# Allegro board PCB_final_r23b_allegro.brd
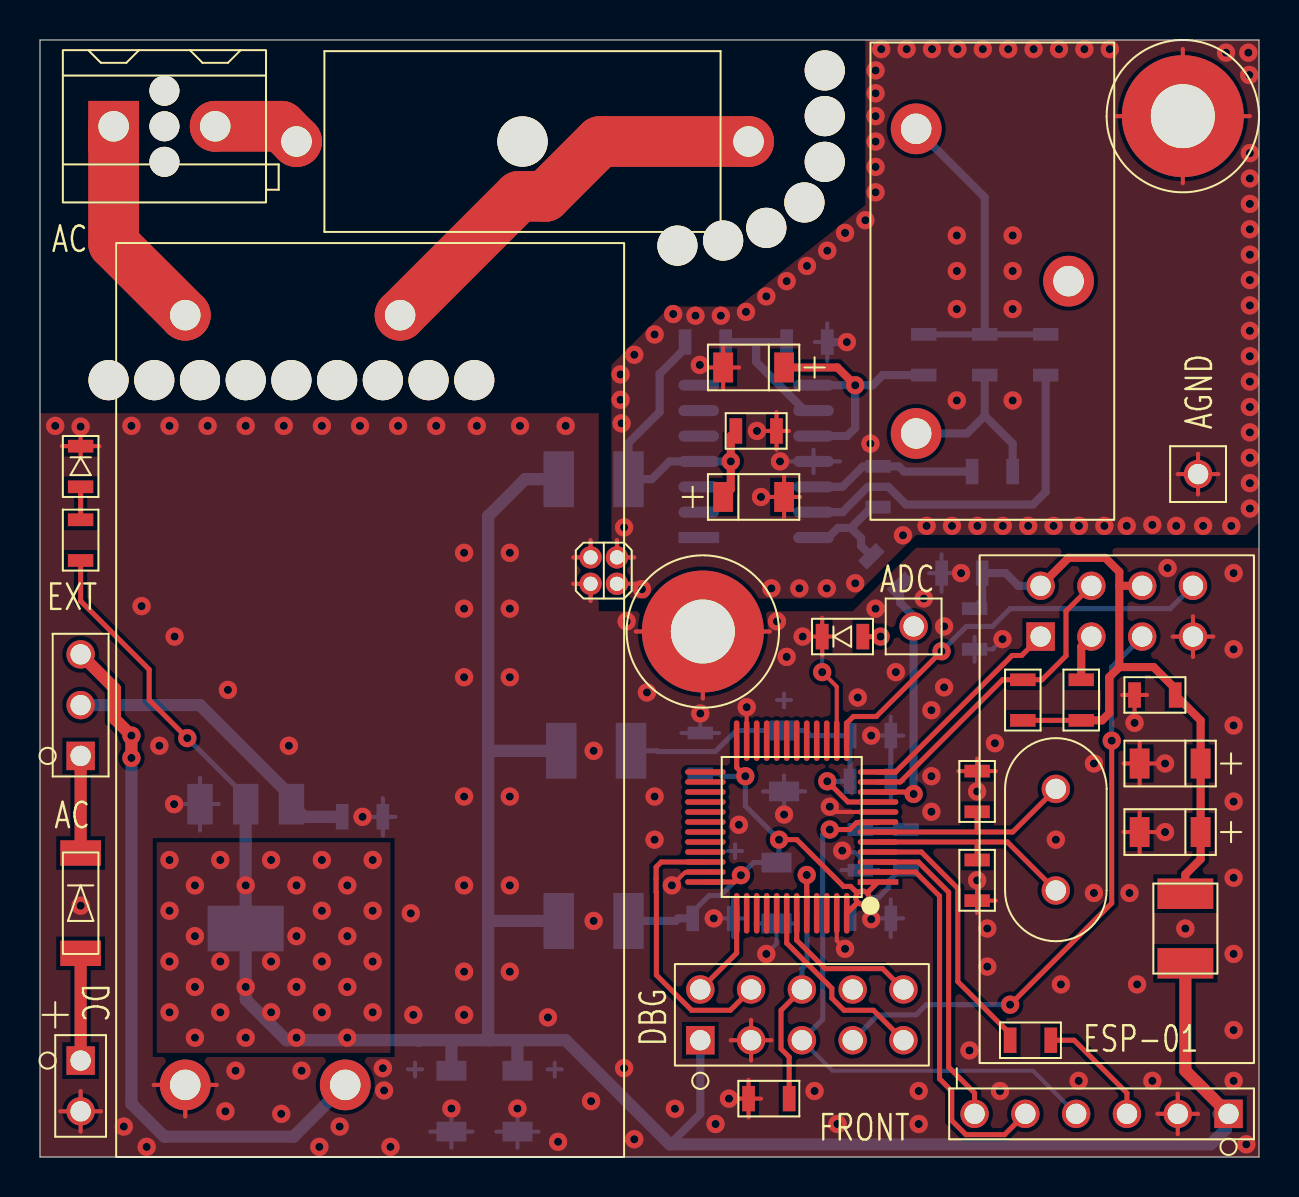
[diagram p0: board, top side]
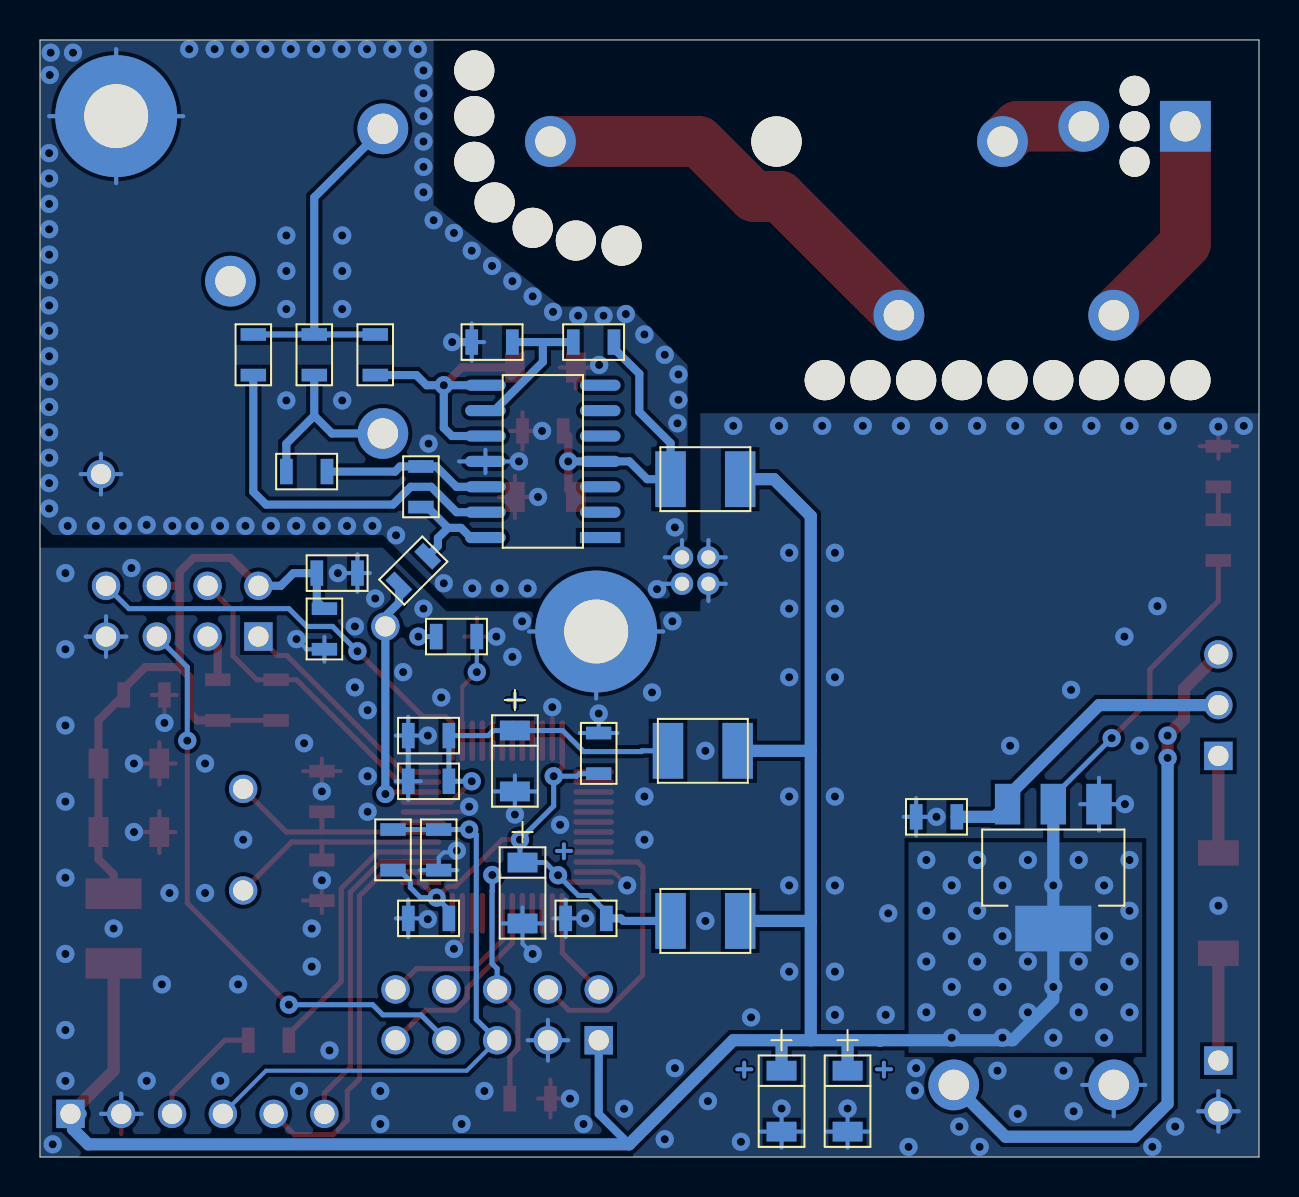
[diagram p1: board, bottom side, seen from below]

Outline 60.96 x 55.88 mm; copper layers: TOP, IN1, IN2, BOTTOM. Coordinates in mm from the lower left corner of the outline.
Outline path: 0,55.88 0,0 60.96,0 60.96,55.88 0,55.88

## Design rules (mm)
net group DP1: nets USB_DM USB_DP

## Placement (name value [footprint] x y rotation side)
C4  100n  [S_0805]  16.13 17.02 0 bottom
C5  10u  [S_1206_CAP]  23.88 2.79 270 bottom
C8  10u  [S_1206_CAP]  36.83 13.21 270 bottom
C9  100n  [S_0805]  33.66 11.94 0 bottom
C10  100n  [S_0805]  41.53 11.94 0 bottom
C11  100n  [S_0805]  33.02 20.19 90 bottom
C12  100n  [S_0805]  41.02 15.37 270 bottom
C16  10u  [S_1206_CAP]  35.69 39.5 180 top
C17  22p  [S_0805]  46.86 13.84 270 top
C18  22p  [S_0805]  46.86 18.29 90 top
C22  100n  [S_0805]  35.81 36.32 0 top
C23  10n  [S_0805]  46.74 26.42 270 bottom
C24  10u  [S_1206_CAP]  56.52 19.68 180 top
C25  10u  [S_1206_CAP]  20.57 2.79 270 bottom
C26  100n  [S_0805]  55.75 23.11 180 top
C27  100n  [S_0805]  46.1 29.21 180 bottom
C28  10u  [S_1206_CAP]  35.69 33.02 0 top
C29  10u  [S_1206_CAP]  37.21 19.81 270 bottom
C30  10n  [S_0805]  41.53 21.08 0 bottom
C31  100n  [S_0805]  41.53 18.8 0 bottom
C32  10u  [S_1206_CAP]  56.52 16.26 180 top
D1  SUF4007  [S_MELF]  2.03 12.7 270 top
F1  FUSEHOLDER  [T_FUSE]  24.13 50.8 0 top
H1  MOUNT HOLE M3  [MOUNT_HOLE_M3]  57.15 52.07 0 top
H2  MOUNT HOLE M3  [MOUNT_HOLE_M3]  33.15 26.29 0 top
J1  AC  [T_POWER_CON]  6.22 51.56 0 top
J2  PWR_SELECT  [T_SIP3]  2.03 22.61 180 top
J3  EXT_12V  [T_SIP2]  2.03 4.83 0 top
J16  FRONT  [T_SIP6]  59.44 2.16 270 top
J17  DEBUG_PORT  [T_HEADER5X2]  38.1 7.11 90 top
L2  27uH  [S_1210]  27.69 33.91 0 bottom
L4  27uH  [S_1210]  27.69 11.81 0 bottom
L5  27uH  [S_1210]  57.28 11.43 90 top
L6  27uH  [S_1210]  27.81 20.32 0 bottom
LD1  D1  [S_0805_LED]  40.13 26.04 0 top
LD3  POWER  [S_0805_LED]  2.03 34.54 270 top
NOREF  -  [unnamed]  21.72 38.86 0 top
NOREF#2  -  [unnamed]  10.29 38.86 0 top
NOREF#3  -  [unnamed]  5.71 38.86 0 top
NOREF#4  -  [unnamed]  36.32 46.48 0 top
NOREF#5  -  [#2]  0 0 0 top
NOREF#6  -  [unnamed]  39.24 52.07 0 top
NOREF#7  -  [unnamed]  8 38.86 0 top
NOREF#8  -  [unnamed]  39.24 49.78 0 top
NOREF#9  -  [unnamed]  19.43 38.86 0 top
NOREF#10  -  [#2]  0 0 90 top
NOREF#11  -  [unnamed]  12.57 38.86 0 top
NOREF#12  -  [unnamed]  14.86 38.86 0 top
NOREF#13  -  [unnamed]  3.43 38.86 0 top
NOREF#14  -  [unnamed]  38.23 47.75 0 top
NOREF#15  -  [unnamed]  31.88 45.59 0 top
NOREF#16  -  [unnamed]  39.24 54.36 0 top
NOREF#17  -  [unnamed]  34.16 45.85 0 top
NOREF#18  -  [unnamed]  17.14 38.86 0 top
R3  470  [S_0805]  40.13 26.04 0 bottom
R5  150  [S_0805]  2.03 30.86 90 top
R6  100R  [S_0805]  47.24 40.13 270 bottom
R7  10k  [S_0805]  47.62 34.29 180 bottom
R8  100k  [S_0805]  41.91 33.53 270 bottom
R9  470R  [S_0805]  42.29 29.34 315 bottom
R10  1K  [S_0805]  33.27 40.77 0 bottom
R11  1K  [S_0805]  38.35 40.77 0 bottom
R19  10k  [S_0805]  36.45 2.92 0 top
R20  100k  [S_0805]  49.15 22.86 270 top
R21  100k  [S_0805]  52.07 22.86 270 top
R22  100k  [S_0805]  43.31 15.37 90 bottom
R23  470  [S_0805]  49.53 5.84 180 top
R24  470R  [S_0805]  44.2 40.13 270 bottom
R25  10k  [S_0805]  50.29 40.13 270 bottom
SB1  AGND BRIDGE  [T_AGND_BRIDGE]  28.19 29.34 180 top
TP1  TEST POINT  [T_TESTPOINT]  43.69 26.54 0 top
TP2  TEST POINT  [T_TESTPOINT]  57.91 34.16 0 top
TR1  AC-1010  [T_TALEMA_CUR_TR]  47.62 43.81 90 top
U1  MeanWell IRM-10-12  [T_MEANWELL_PSU]  16.51 22.86 270 top
U3  LD1117AS33TR  [S_SOT223]  10.29 17.65 270 bottom
U5  STM32F303CC  [S_LQFP48]  37.59 16.51 180 top
U6  ESP-01  [ESP01]  53.85 27.3 90 top
U7  AD8544  [S_SOIC14_N]  35.81 34.8 0 bottom
X1  8MHz  [T_XTAL50]  50.8 15.88 90 top

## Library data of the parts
C4 C9-C12 C17 C18 C22 C23 C26 C27 C30 C31 = CAPACITOR NON-POL
C5 C8 C16 C24 C25 C28 C29 C32 = CAP POL
D1 = DIODE
F1 = FUSEHOLDER
H1 H2 = MOUNT HOLE M3
J1 J3 = HEADER 2
J2 = JUMPER 3
J16 = HEADER 6
J17 = HEADER 5X2
L2 L4-L6 = INDUCTOR
LD1 LD3 = LED
R3 R5-R11 R19-R25 = RESISTOR
SB1 = AGND BRIDGE
TP1 TP2 = TEST POINT
TR1 = ac-1010
U1 = meanwell_psu
U3 = LD1117AS33TR
U5 = stm32f303cct6
U6 = ESP-01
U7 = AD8544
X1 = CRYSTAL

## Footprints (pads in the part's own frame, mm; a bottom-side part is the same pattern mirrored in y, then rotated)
ESP01
  rect 1.422x1.422 hole 1.016: 1(-1.27,3.81)
  round 1.422 hole 1.016: 2(1.27,3.81) 3(-1.27,1.27) 4(1.27,1.27) 5(-1.27,-1.27) 6(1.27,-1.27) 7(-1.27,-3.81) 8(1.27,-3.81)
MOUNT_HOLE_M3
  round 6.096 hole 3.2: 1(0,0)
S_0805
  rect 0.635x1.27 smd: 1(-1.016,0) 2(1.016,0)
S_0805_LED
  rect 0.635x1.27 smd: 1(-1.016,0) 2(1.016,0)
S_1206_CAP
  rect 0.991x1.499 smd: 1(-1.524,0) 2(1.524,0)
S_1210
  rect 1.524x2.794 smd: 1(-1.742,0) 2(1.742,0)
S_LQFP48
  rect 2.032x0.279 smd: 1(-4.318,2.752)
  oval 2.032x0.279 smd: 2(-4.318,2.252) 3(-4.318,1.751) 4(-4.318,1.251) 5(-4.318,0.751) 6(-4.318,0.25) 7(-4.318,-0.25) 8(-4.318,-0.751) 9(-4.318,-1.251) 10(-4.318,-1.751) 11(-4.318,-2.252) 12(-4.318,-2.752) 25(4.318,-2.752) 26(4.318,-2.252) 27(4.318,-1.751) 28(4.318,-1.251) 29(4.318,-0.751) 30(4.318,-0.25) 31(4.318,0.25) 32(4.318,0.751) 33(4.318,1.251) 34(4.318,1.751) 35(4.318,2.252) 36(4.318,2.752)
  oval 0.279x2.032 smd: 13(-2.752,-4.318) 14(-2.252,-4.318) 15(-1.751,-4.318) 16(-1.251,-4.318) 17(-0.751,-4.318) 18(-0.25,-4.318) 19(0.25,-4.318) 20(0.751,-4.318) 21(1.251,-4.318) 22(1.751,-4.318) 23(2.252,-4.318) 24(2.752,-4.318) 37(2.752,4.318) 38(2.252,4.318) 39(1.751,4.318) 40(1.251,4.318) 41(0.751,4.318) 42(0.25,4.318) 43(-0.25,4.318) 44(-0.751,4.318) 45(-1.251,4.318) 46(-1.751,4.318) 47(-2.252,4.318) 48(-2.752,4.318)
S_MELF
  rect 1.27x2.032 smd: 1(-2.51,0) 2(2.51,0)
S_SOIC14_N
  rect 2.032x0.559 smd: 1(-2.87,3.81)
  oval 2.032x0.559 smd: 2(-2.87,2.54) 3(-2.87,1.27) 4(-2.87,0) 5(-2.87,-1.27) 6(-2.87,-2.54) 7(-2.87,-3.81) 8(2.87,-3.81) 9(2.87,-2.54) 10(2.87,-1.27) 11(2.87,0) 12(2.87,1.27) 13(2.87,2.54) 14(2.87,3.81)
S_SOT223
  rect 2.032x1.27 smd: 1(0,2.286) 2(0,0) 3(0,-2.286)
  rect 2.286x3.81 smd: 4(6.223,0)
T_AGND_BRIDGE
  round 1.118 hole 0.711: 1(-0.66,0.66) 2(0.66,0.66) 3(-0.66,-0.66) 4(0.66,-0.66)
T_FUSE
  round 2.515 hole 2.54 unplated: (0,0)
  round 2.54 hole 1.524: 1(-11.303,0) 2(11.303,0)
T_HEADER5X2
  rect 1.422x1.422 hole 1.016: 1(-1.27,5.08)
  round 1.422 hole 1.016: 2(1.27,5.08) 3(-1.27,2.54) 4(1.27,2.54) 5(-1.27,0) 6(1.27,0) 7(-1.27,-2.54) 8(1.27,-2.54) 9(-1.27,-5.08) 10(1.27,-5.08)
T_MEANWELL_PSU
  round 2.54 hole 1.524: 1(-19.253,1.499) 2(-19.253,-9.246) 3(19.253,-1.245) 4(19.253,-9.246)
T_POWER_CON
  round 1.499 hole 1.524 unplated: (0,1.778) (0,0) (0,-1.778)
  rect 2.54x2.54 hole 1.524: 1(-2.54,0)
  round 2.54 hole 1.524: 2(2.54,0)
T_SIP2
  rect 1.422x1.422 hole 1.016: 1(0,0)
  round 1.422 hole 1.016: 2(0,-2.54)
T_SIP3
  rect 1.422x1.422 hole 1.016: 1(0,2.54)
  round 1.422 hole 1.016: 2(0,0) 3(0,-2.54)
T_SIP6
  rect 1.422x1.422 hole 1.016: 1(0,0)
  round 1.422 hole 1.016: 2(0,-2.54) 3(0,-5.08) 4(0,-7.62) 5(0,-10.16) 6(0,-12.7)
T_TALEMA_CUR_TR
  round 2.54 hole 1.524: 1(-7.62,3.81) 2(7.62,3.81) X1(0,-3.81)
T_TESTPOINT
  round 1.422 hole 1.016: 1(0,0)
T_XTAL50
  round 1.422 hole 1.016: 1(-2.54,0) 2(2.54,0)
unnamed
  round 2.007 hole 2.032 unplated: (0,0)

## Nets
3V3: C5.1 C25.1 J16.1 J17.1 L2.1 L4.1 L5.1 L6.1 R5.1 U3.2(VOUT) U3.4(TAB_VOUT)
3V3_ADC: C29.1 C30.1 C31.1 L6.2 U5.9(VDDA)
3V3_ANALOG: C22.1 C28.1 L2.2 R10.1 U7.4(VCC)
3V3_CPU: C8.1 C9.1 C10.1 C11.1 L4.2 R22.1 U5.1(VBAT) U5.24(VDD#24) U5.36(VDD#36) U5.48(VDD#48)
3V3_ESP: C23.1 C24.1 C26.1 C27.1 C32.1 L5.2 R20.2 R21.2 U6.2(VCC) U6.6(CHPD)
12V: C4.1 J2.2(P2) U3.3(VIN)
GND: C4.2 C5.2 C8.2 C9.2 C10.2 C11.2 C12.2 C17.2 C18.2 C23.2 C24.2 C25.2 C26.2 C27.2 C29.2 C30.2 C31.2 C32.2 H2.1 J3.2 J16.2 J17.3 LD1.1(CATHODE) LD3.1(CATHODE) R19.1 SB1.2(B1) SB1.4(B2) U1.4(GND) U3.1(GND) U5.8(VSSA) U5.23(VSS#23) U5.35(VSS#35) U5.47(VSS#47) U6.7(GND)
GNDA: C16.2 C22.2 C28.2 H1.1 R11.2 SB1.1(A1) SB1.3(A2) TP2.1 U7.11(GND)
ADC_IN: R9.2 TP1.1 U5.10(PA0)
BOOT0: J17.6 R19.2 U5.44(BOOT0)
BTN_AP: J16.5 U5.2(PC13)
BTN_WPS: J16.6 U5.3(PC14/OSC32_IN)
DBG_RX: J17.10 U5.43(PB7)
DBG_TX: J17.9 U5.42(PB6)
ESP_DBG_TX: J17.7 U6.5(GPIO2)
ESP_NRST: R20.1 U5.11(PA1) U6.4(RST)
ESP_RX: U5.12(PA2) U6.1(RX)
ESP_TX: U5.13(PA3) U6.8(TX)
PA4: R3.1 U5.14(PA4)
PA5: U5.15(PA5)
PA6: U5.16(PA6)
PA7: U5.17(PA7)
PA8: U5.29(PA8)
PA9: U5.30(PA9)
PA10: U5.31(PA10)
PA13: J17.4 U5.34(PA13)
PA14: J17.2 U5.37(PA14)
PA15: U5.38(PA15)
PB0: U5.18(PB0)
PB1: U5.19(PB1)
PB2: U5.20(PB2)
PB3: U5.39(PB3)
PB4: U5.40(PB4)
PB5: U5.41(PB5)
PB8: U5.45(PB8)
PB9: U5.46(PB9)
PB10: U5.21(PB10)
PB11: U5.22(PB11)
PB12: U5.25(PB12)
PB13: U5.26(PB13)
PB14: U5.27(PB14)
PB15: U5.28(PB15)
PC15: R23.2 U5.4(PC15/OSC32_OUT)
STM_NRST: C12.1 J16.4 J17.5 R22.2 U5.7(NRST)
USB_DM: U5.32(PA11)
USB_DP: U5.33(PA12)
N50776: F1.1 J1.2
N50985: J2.3(P3) U1.3(12V)
N125461: R7.2 R8.1 U7.12(P)
N125469: R8.2 R9.1 U7.14(Y)
N125661: R10.2 R11.1 U7.9(N)
N125707: C16.1 R24.2 U7.8(Y) U7.10(P)
N128674: C18.1 U5.6(PF1/OSC_OUT) X1.2
N128682: C17.1 U5.5(PF0/OSC_IN) X1.1
N134498: R21.1 U6.3(GPIO0)
N141672: J16.3 R23.1
N147532: D1.2(A) J3.1
N147956: D1.1(K) J2.1(P1)
N153457: J1.1 U1.2(AC/L)
N158713: R25.2 U7.13(N)
N165035: R6.2 R7.1 TR1.1
N165680: R6.1 R24.1 R25.1 TR1.2
N507430: F1.2 U1.1(AC/N)
N1337610: LD3.2(ANODE) R5.2
N1355460: LD1.2(ANODE) R3.2

Pads without a net: J17 8; TR1 X1; U7 1 2 3 5 6 7

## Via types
v1: diameter 0.914, hole 0.406, TOP to BOTTOM, 257 vias

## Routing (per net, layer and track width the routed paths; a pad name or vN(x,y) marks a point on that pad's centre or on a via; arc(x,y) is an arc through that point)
3V3: length 134
  TOP w0.254: v1(7.37,20.95) 5.46,22.86 5.46,24.38 2.03,27.81 R5.1
  TOP w0.61: L5.1 57.28,4.32 J16.1
  BOTTOM w0.254: U3.2 10.29,18.03 v1(7.37,20.95)
  BOTTOM w0.406: 31.5,0.64 33.02,2.16 J17.1
  BOTTOM w0.61: L6.1 22.42,20.32 22.42,20.32 ; 22.42,20.32 22.42,32.07 24.26,33.91 L2.1 ; 22.42,20.32 22.42,11.81 ; 59.31,1.78 59.31,1.4 58.55,0.64 31.5,0.64 26.29,5.84 23.88,5.84 ; 59.31,1.78 59.31,2.03 J16.1 ; 59.31,1.78 58.93,2.16 ; 20.57,5.84 18.97,5.84 18.95,5.82 18.92,5.84 12.32,5.84 10.29,7.87 ; 20.57,5.84 22.42,5.84 ; 20.57,5.84 C25.1 ; 22.42,5.84 22.42,11.81 ; 22.42,5.84 23.88,5.84 ; 22.42,11.81 L4.1 ; 23.88,5.84 C5.1 ; 10.29,8 v1(10.29,8.51) U3.4 v1(10.29,13.59) U3.2
  vias: v1(6.48,14.86) v1(6.48,12.32) v1(6.48,9.78) v1(6.48,7.24) v1(7.75,13.59) v1(7.75,11.05) v1(7.75,8.51) v1(7.75,5.97) v1(9.02,14.86) v1(9.02,9.78) v1(9.02,7.24) v1(10.29,5.97) v1(11.56,14.86) v1(11.56,9.78) v1(11.56,7.24) v1(12.83,13.59) v1(12.83,11.05) v1(12.83,8.51) v1(12.83,5.97) v1(14.1,14.86) v1(14.1,12.32) v1(14.1,9.78) v1(14.1,7.24) v1(15.37,13.59) v1(15.37,11.05) v1(15.37,8.51) v1(15.37,5.97) v1(16.64,14.86) v1(16.64,12.32) v1(16.64,9.78) v1(16.64,7.24)
3V3_ADC: length 17.9
  TOP w0.254: U5.9 40.41,17.76 v1(39.37,18.8)
  BOTTOM w0.254: L6.2 30.86,20.32 30.9,20.28 33.77,20.28 34.83,21.34 C29.1 38.29,21.34 38.54,21.08 40.51,21.08 40.51,18.8 v1(39.37,18.8)
3V3_ANALOG: length 17.1
  TOP w0.406: C22.1 34.54,36.07 v1(34.54,34.8) 34.54,33.4 C28.1
  BOTTOM w0.406: v1(34.54,34.8) U7.4 31.49,34.8 30.6,33.91 L2.2 29.43,35.71 30.99,37.27 30.99,39.18 32.26,40.45 R10.1
3V3_CPU: length 31.9
  TOP w0.254: v1(35.05,14.1) 34.71,13.76 U5.36 ; v1(35.27,19.05) 34.84,19.48 U5.24 ; U5.1 41.13,12.97 ; 41.13,12.97 U5.48 ; 41.13,12.97 v1(41.13,12.97) 40.81,13.29 40.79,13.29 40.54,13.54 40.18,13.54 37.85,15.88 v1(36.96,15.88)
  BOTTOM w0.254: C11.1 33.99,19.18 34.11,19.05 v1(35.27,19.05) 35.27,17.56 v1(36.96,15.88) 36.96,14.86 C8.1 35.69,14.73 v1(35.05,14.1) 34.04,13.08 33.46,13.08 32.64,12.26 C9.1 ; R22.1 42.99,14.35 42.44,13.8 42.44,13.48 41.93,12.97 v1(41.13,12.97) 40.51,12.36 40.51,11.94
  BOTTOM w0.406: C9.1 31.92,11.94 31.79,11.81 L4.2
3V3_ESP: length 37.2
  TOP w0.254: R20.2 R21.2
  TOP w0.406: 53.98,24.51 53.47,24 53.47,22.2 53.11,21.84 R21.2 ; 53.98,24.51 55.69,24.51 56.77,23.43 C26.1 58.04,21.84 C24.1 C32.1 58.04,14.9 57.28,14.14 L5.2 ; 53.98,24.51 53.98,28.57 ; 53.98,28.57 53.98,29.27 53.27,29.97 51.44,29.97 U6.2 ; 53.98,28.57 U6.6
  BOTTOM w0.406: U6.2 48.92,28.57 48.29,29.21 C27.1 47.12,27.81 C23.1
12V: length 15.6
  BOTTOM w0.61: 15.11,17.02 13.21,17.02 U3.3 12.57,18.03 8,22.61 J2.2
GND: length 155.7
  TOP w0.203: 7.26,2.03 U1.4 ; U1.4 8.84,3.61 ; U1.4 5.69,3.61 ; v1(39.5,17.53) 39.76,17.26 U5.8 ; 55.88,2.16 J16.2 ; J16.2 56.9,1.14 ; J16.2 57.91,2.16 ; J16.2 56.9,3.18 ; v1(54.74,21.72) C26.2 ; C26.2 54.11,23.11 ; C26.2 55.36,23.11 ; v1(56.26,19.68) C24.2 ; C24.2 54.19,19.68 ; C24.2 54.99,20.74 ; C24.2 54.99,18.63 ; U5.35 32.29,14.26 32.24,14.2 32.21,14.2 31.6,13.59 v1(31.6,13.59) ; 29.79,26.29 H2.1 ; H2.1 36.5,26.29 ; H2.1 33.15,22.94 ; 34.54,5.84 J17.3 ; J17.3 35.56,4.83 ; J17.3 35.56,6.86 ; J17.3 36.58,5.84 ; J3.2 3.05,2.29 ; J3.2 2.03,1.27 ; J3.2 2.03,3.3 ; J3.2 1.02,2.29 ; LD3.1 v1(2.03,36.54) ; LD3.1 2.03,34.94 ; LD3.1 1.09,35.56 ; LD3.1 2.97,35.56 ; v1(56.26,16.26) C32.2 ; C32.2 54.99,15.2 ; C32.2 54.99,17.31 ; C32.2 54.19,16.26 ; U6.7 57.66,27.05 ; U6.7 56.64,26.04 ; U6.7 58.67,26.04 ; U6.7 57.66,25.02 ; LD1.1 39.74,26.04 ; LD1.1 v1(38.14,26.04) ; LD1.1 39.12,26.98 ; LD1.1 39.12,25.09 ; C18.2 46.86,19.93 ; C18.2 v1(46.86,18.29) ; C18.2 47.8,19.3 ; C18.2 45.92,19.3 ; R19.1 36.06,2.92 ; R19.1 35.43,3.86 ; R19.1 v1(34.46,2.92) ; R19.1 35.43,1.98 ; 46.86,12.2 C17.2 ; C17.2 v1(46.86,13.84) ; C17.2 47.8,12.83 ; U5.23 v1(35.34,22.5) ; 27.53,30.86 SB1.4 26.67,30 ; 26.67,28.68 SB1.2 27.53,27.81 ; U5.47 39.84,10.83 v1(40.26,10.41)
  BOTTOM w0.203: C9.2 34.67,12.88 ; C9.2 35.29,11.94 ; C9.2 34.67,11 ; C9.2 v1(33.69,11.94) ; 19.52,1.27 C25.2 ; C25.2 20.57,0.47 ; C25.2 21.63,1.27 ; C25.2 v1(20.57,2.43) ; C29.2 38.27,18.29 ; C29.2 36.16,18.29 ; C29.2 v1(37.21,17.13) ; C29.2 37.21,19.09 ; C12.2 41.02,14.99 40.77,15.24 40.26,15.24 40.17,15.33 v1(40.12,15.33) ; C12.2 40.08,14.35 ; C12.2 41.96,14.35 ; C23.2 47.62,25.4 ; C23.2 46.74,24.78 ; C23.2 46.74,26.02 ; 47.62,25.4 v1(48.13,25.91) ; 47.62,25.4 47.68,25.4 ; 8,17.65 v1(6.71,17.65) ; 8,17.65 8,18.97 ; 8,17.65 8,16.33 ; 8,17.65 8.94,17.65 ; U1.4 8.84,3.61 ; U1.4 5.69,3.61 ; U1.4 7.26,2.03 ; H2.1 36.5,26.29 ; H2.1 33.15,22.94 ; H2.1 29.79,26.29 ; 26.67,30 SB1.4 27.53,30.86 ; C30.2 43.17,21.08 ; C30.2 v1(41.57,21.08) ; C30.2 42.55,22.02 ; J16.2 56.9,3.18 ; J16.2 57.91,2.16 ; J16.2 55.88,2.16 ; 23.88,0.47 C5.2 ; C5.2 24.93,1.27 ; C5.2 22.82,1.27 ; C5.2 v1(23.88,2.43) ; 17.14,17.02 17.77,17.02 ; 17.14,17.02 v1(16.13,17.02) ; 17.14,17.02 17.14,17.96 ; 17.14,17.02 17.14,16.08 ; 42.55,17.86 C31.2 ; C31.2 43.17,18.8 ; C31.2 41.92,18.8 ; 57.66,25.02 U6.7 ; U6.7 57.66,27.05 ; U6.7 58.67,26.04 ; U6.7 56.64,26.04 ; C27.2 v1(46.06,29.21) ; C27.2 45.09,28.27 ; C27.2 45.09,30.15 ; C27.2 44.46,29.21 ; C10.2 42.55,12.88 ; C10.2 42.55,11 ; C10.2 43.17,11.94 ; C10.2 41.57,11.94 v1(41.57,11.89) ; C8.2 37.88,11.68 ; C8.2 36.83,10.67 v1(36.32,10.16) ; C8.2 36.83,12.48 ; C8.2 35.78,11.68 ; J17.3 35.56,6.86 ; J17.3 34.54,5.84 ; J17.3 35.56,4.83 ; J17.3 36.58,5.84 ; 1.02,2.29 J3.2 ; J3.2 2.03,3.3 ; J3.2 2.03,1.27 ; J3.2 3.05,2.29 ; 27.53,27.81 SB1.2 26.67,28.68 ; 33.02,21.21 33.96,21.21 ; 33.02,21.21 32.08,21.21 ; 33.02,21.21 v1(33.02,22.19)
  BOTTOM w0.254: C31.2 C30.2
  vias: v1(0.76,36.58) v1(2.03,12.57) v1(4.19,1.52) v1(4.57,36.58) v1(5.08,27.56) v1(5.33,0.51) v1(5.97,20.57) v1(6.48,36.58) v1(6.73,26.04) v1(8.38,36.58) v1(9.27,2.29) v1(9.4,23.37) v1(9.78,4.32) v1(10.29,36.58) v1(12.06,2.16) v1(12.19,36.58) v1(12.45,20.57) v1(13.08,4.32) v1(13.97,0.51) v1(14.1,36.58) v1(14.99,1.52) v1(16,36.58) v1(17.14,4.45) v1(17.21,3.33) v1(17.53,0.51) v1(17.91,36.58) v1(18.54,12.19) v1(18.67,7.11) v1(19.81,36.58) v1(21.21,30.23) v1(21.21,27.43) v1(21.21,24) v1(21.21,18.03) v1(21.21,13.59) v1(21.21,9.27) v1(21.21,7.11) v1(21.84,36.58) v1(23.5,30.23) v1(23.5,27.43) v1(23.5,24) v1(23.5,18.03) v1(23.5,13.59) v1(23.5,9.27) v1(24,36.58) v1(25.4,6.99) v1(25.91,0.76) v1(26.29,36.58) v1(27.56,2.79) v1(27.69,20.32) v1(27.69,11.81) v1(29.21,4.45) v1(29.34,26.8) v1(29.72,0.89) v1(30.35,23.24) v1(30.73,18.03) v1(30.73,15.88) v1(31.75,2.41) v1(33.78,1.65) v1(34.95,16.62) v1(36.85,26.8) v1(37.34,25.02) v1(38.73,3.3) v1(39.88,1.65) v1(40.89,22.99) v1(41.78,27.43) v1(42.8,24.26) v1(43.94,3.3) v1(43.94,1.65) v1(44.2,27.94) v1(44.58,22.35) v1(44.58,19.05) v1(44.58,17.27) v1(45.21,26.54) v1(45.21,23.5) v1(46.48,5.33) v1(47.37,11.43) v1(47.37,9.53) v1(47.75,20.7) v1(48.01,3.3) v1(50.8,15.88) v1(51.05,8.64) v1(51.94,3.81) v1(52.7,19.68) v1(52.7,13.21) v1(54.48,13.21) v1(54.86,8.64) v1(55.63,3.81) v1(56.39,29.46) v1(57.28,11.43) v1(59.69,29.21) v1(59.69,25.4) v1(59.69,21.59) v1(59.69,17.78) v1(59.69,13.97) v1(59.69,10.16) v1(59.69,6.35) v1(59.69,3.81) v1(60.33,0.64)
GNDA: length 59.7
  TOP w0.203: C16.2 33.26,39.5 33.13,39.62 v1(33,39.62) ; C16.2 34.16,40.55 ; C16.2 34.96,39.5 ; C16.2 34.16,38.44 ; C28.2 38.01,33.02 ; C28.2 37.21,34.07 ; C28.2 v1(36.06,33.02) ; C28.2 37.21,31.97 ; H1.1 57.15,55.42 ; H1.1 60.5,52.07 ; H1.1 57.15,48.72 ; H1.1 53.8,52.07 ; SB1.1 29.82,28.68 ; C22.2 v1(35.85,36.32) ; C22.2 37.45,36.32 ; C22.2 36.83,35.38 ; C22.2 36.83,37.26 ; 56.9,34.16 TP2.1 ; TP2.1 57.91,33.15 ; TP2.1 58.93,34.16 ; TP2.1 57.91,35.18 ; 28.85,30.86 SB1.3 29.72,30
  BOTTOM w0.203: U7.11 40.01,34.8 ; U7.11 38.68,35.38 ; U7.11 38.68,34.21 ; U7.11 v1(37.01,34.8) ; 57.15,48.72 H1.1 ; H1.1 57.15,55.42 ; H1.1 53.8,52.07 ; H1.1 60.5,52.07 ; TP2.1 57.91,35.18 ; TP2.1 57.91,33.15 ; TP2.1 58.93,34.16 ; TP2.1 56.9,34.16 ; 39.37,39.83 R11.2 ; R11.2 39.37,41.71 ; R11.2 38.75,40.77 ; 28.85,30.86 SB1.3 29.72,30 ; SB1.1 29.82,28.68
  BOTTOM w0.406: R11.2 v1(40.35,40.77)
  vias: v1(29.03,39.15) v1(29.03,37.88) v1(29.08,36.7) v1(29.21,31.5) v1(29.72,40.13) v1(30.1,28.41) v1(30.73,41.15) v1(31.66,42.17) v1(32.78,42.09) v1(34.05,42.09) v1(35.3,42.28) v1(36.32,43.05) v1(36.58,28.45) v1(37.34,43.81) v1(37.97,28.45) v1(38.35,44.58) v1(39.35,28.45) v1(39.37,45.34) v1(40.26,46.23) v1(40.77,28.7) v1(41.27,46.86) v1(41.53,35.69) v1(41.78,54.36) v1(41.78,53.21) v1(41.78,52.07) v1(41.78,50.8) v1(41.78,49.53) v1(41.78,48.26) v1(42.07,55.42) v1(43.16,31.1) v1(43.34,55.42) v1(44.34,31.57) v1(44.61,55.42) v1(45.61,31.57) v1(45.85,46.1) v1(45.85,44.32) v1(45.85,42.42) v1(45.85,37.85) v1(45.88,55.42) v1(46.88,31.57) v1(47.15,55.42) v1(48.15,31.57) v1(48.42,55.42) v1(48.64,46.1) v1(48.64,44.32) v1(48.64,42.42) v1(48.64,37.85) v1(49.42,31.57) v1(49.69,55.42) v1(50.69,31.57) v1(50.96,55.42) v1(51.96,31.57) v1(52.23,55.42) v1(53.23,31.57) v1(53.5,55.42) v1(54.34,31.57) v1(55.63,31.62) v1(56.82,31.57) v1(58.17,31.57) v1(59.31,55.24) v1(59.58,31.57) v1(60.43,55.24) v1(60.47,54.13) v1(60.5,50.22) v1(60.5,48.95) v1(60.5,47.68) v1(60.5,46.41) v1(60.5,45.14) v1(60.5,43.87) v1(60.5,42.6) v1(60.5,41.33) v1(60.5,40.06) v1(60.5,38.79) v1(60.5,37.52) v1(60.5,36.25) v1(60.5,34.98) v1(60.5,33.71) v1(60.5,32.44)
ADC_IN: length 12.6
  TOP w0.254: U5.10 43.53,18.26 43.53,18.21 43.64,18.21 v1(43.69,18.16)
  BOTTOM w0.406: v1(43.69,18.16) TP1.1 43.56,26.67 43.56,27.18 43.01,27.73 R9.2
BOOT0: length 13.8
  TOP w0.254: J17.6 37.06,7.34 37.06,5.41 37.47,5 R19.2 ; v1(38.34,14.11) U5.44
  BOTTOM w0.254: v1(38.34,14.11) 38.34,13.32 38.35,13.31 38.35,9.68 38.1,9.42 J17.6
BTN_AP: length 19.5
  TOP w0.254: 49.28,2.16 48.23,1.12 46.3,1.12 45.59,1.83 45.59,3.3 44.98,3.91 44.98,13.06 43.78,14.26 U5.2
BTN_WPS: length 15.8
  TOP w0.254: U5.3 43.93,14.76 45.44,13.25 45.44,4.5 46.74,3.2 46.74,2.16
DBG_RX: length 7.7
  TOP w0.254: U5.43 37.84,10.85 39.26,9.42 42.14,9.42 J17.10
DBG_TX: length 9.6
  TOP w0.254: J17.9 41.68,7.34 40.21,7.34 39.6,7.95 39.6,8.44 37.34,10.7 U5.42
ESP_DBG_TX: length 29.8
  TOP w0.254: v1(53.59,20.83) 53.59,12.7 v1(48.51,7.62)
  BOTTOM w0.254: U6.5 53.59,24.51 v1(53.59,20.83) ; v1(48.51,7.62) 44.32,7.62 43.81,7.11 41.91,7.11 J17.7
ESP_NRST: length 16
  TOP w0.254: U5.11 43.02,18.76 48.13,23.88 R20.1 50.11,23.88 51.31,25.07 51.31,27.3 U6.4
ESP_RX: length 10.9
  TOP w0.254: U6.1 49.09,25.09 48.61,25.09 42.79,19.26 U5.12
ESP_TX: length 21
  TOP w0.254: v1(45.09,25.3) 41.82,22.04 40.68,22.04 40.34,21.7 U5.13
  BOTTOM w0.254: v1(45.09,25.3) 46.33,26.54 47.63,26.54 48.51,27.43 56.52,27.43 U6.8
PA4: length 5.5
  TOP w0.203: U5.14 39.84,23.53 v1(39.12,24.26)
  BOTTOM w0.203: v1(39.12,24.26) R3.1
PA13: length 13.9
  TOP w0.254: J17.4 34.52,7.34 32.59,7.34 30.82,9.1 30.82,13.25 30.81,13.26 30.81,13.93 30.81,14.5 31.06,14.76 U5.34
PA14: length 4.6
  TOP w0.254: U5.37 34.84,10.2 J17.2
PC15: length 13.4
  TOP w0.254: U5.4 44.07,15.26 45.9,13.43 45.9,8.78 48.51,6.16 R23.2
STM_NRST: length 32.8
  TOP w0.254: U5.7 41.88,16.73 40.84,16.73 40.49,16.38 v1(39.5,16.38)
  BOTTOM w0.203: J17.5 39.62,4.32 49.66,4.32 51.82,2.16
  BOTTOM w0.254: J17.5 39.14,6.88 39.14,16.13 39.4,16.38 v1(39.5,16.38) C12.1 R22.2
N50776: length 4.4
  TOP w2.54: 12.83,50.8 12.06,51.56 J1.2
N50985: length 36
  TOP w0.61: J2.3 3.75,23.43 3.75,21.91 v1(4.57,21.08) v1(4.57,19.96)
  BOTTOM w0.61: U1.3 12.67,1.02 6.22,1.02 4.57,2.67 v1(4.57,19.96)
N125461: length 8.5
  BOTTOM w0.406: U7.12 40.13,33.53 41.15,34.54 R8.1 42.95,34.54 43.21,34.29 R7.2
N125469: length 5.7
  BOTTOM w0.406: R8.2 41.59,32.51 40.55,31.47 ; 40.55,31.47 39.91,31.47 39.42,30.99 U7.14 ; 40.55,31.47 41.06,30.97 41.06,30.57 R9.1
N125661: length 7.9
  BOTTOM w0.406: R11.1 35.81,40.77 ; 35.81,40.77 R10.2 ; 35.81,40.77 35.81,39.77 38.25,37.34 U7.9
N125707: length 14
  TOP w0.406: v1(40.77,38.61) 39.88,39.5 C16.1
  BOTTOM w0.406: v1(40.77,38.61) 40.77,36.47 40.36,36.07 U7.10 ; v1(40.77,38.61) U7.8 ; v1(40.77,38.61) 41.63,38.61 42.14,39.12 R24.2
N128674: length 10.8
  TOP w0.254: 46.86,16.26 C18.1 ; 46.86,16.26 48.64,16.26 X1.2 ; 46.86,16.26 U5.6
N128682: length 10.8
  TOP w0.254: X1.1 48.38,15.76 46.86,15.76 ; 46.86,15.76 U5.5 ; 46.86,15.76 C17.1
N134498: length 2.4
  TOP w0.406: R21.1 52.07,25.53 U6.3
N141672: length 5.9
  TOP w0.254: R23.1 51.71,5.84 54.36,3.2 54.36,2.16
N147532: length 5.4
  TOP w0.61: J3.1 D1.2
N147956: length 4.9
  TOP w0.61: D1.1 J2.1
N153457: length 10.9
  TOP w2.54: J1.1 3.68,45.69 U1.2
N158713: length 18.6
  BOTTOM w0.406: R25.2 50.29,33.27 49.66,32.64 43.31,32.64 42.42,33.53 41.4,33.53 40.13,32.26 U7.13
N165035: length 9.2
  BOTTOM w0.406: 47.24,37.08 46.35,36.2 TR1.1 ; 47.24,37.08 48.64,35.69 R7.1 ; 47.24,37.08 R6.2
N165680: length 17.8
  BOTTOM w0.305: R24.1 R6.1 R25.1
  BOTTOM w0.406: 43.81,51.44 47.24,48.01 R6.1
N507430: length 21
  TOP w2.54: F1.2 28.01,50.8 25.27,48.06 23.95,48.06 U1.1
N1337610: length 1.7
  TOP w0.254: 2.03,31.88 LD3.2
N1355460: length 1.8
  TOP w0.254: v1(42.04,26.04) LD1.2
  BOTTOM w0.254: LD1.2 v1(42.04,26.04)

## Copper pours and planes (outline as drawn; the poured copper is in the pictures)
3V3 on TOP, BOTTOM: 5.84,15.75 5.84,5.21 17.53,5.21 17.53,15.75
GND on TOP: 0,0 0,37.21 27.94,37.21 27.94,27.3 40.64,27.3 43.81,30.48 60.96,30.48 60.96,0 ; 4 cut-outs
GND on BOTTOM: 0,0 0,37.21 27.94,37.21 27.94,27.3 40.64,27.3 43.81,30.48 60.96,30.48 60.96,0 ; 1 cut-out
GNDA on TOP, BOTTOM: 41.27,55.88 60.96,55.88 60.96,31.75 60.33,31.11 43.81,31.11 40.64,27.94 28.57,27.94 28.57,39.62 31.5,42.55 34.92,42.55 41.27,47.62

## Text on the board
Board Geometry/Soldermask Bottom: BP 2016 | CVUT FEL | K338 | rev 23 | Ondrej | Hruska | AC current | analyser
Ref Des/Silkscreen Top: EXT | AC | FRONT | ADC | ESP-01 | DBG | AGND | DC
User.7: FIGURE | SIZE | 16.0 | 28.0 | 40.0 | 126.0 | 80.0 | DRILL CHART: TOP to BOTTOM | ALL UNITS ARE IN MILS | PLATED | NON-PLATED | QTY | 234 | 4 | 44 | 2 | 16
